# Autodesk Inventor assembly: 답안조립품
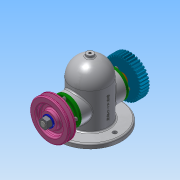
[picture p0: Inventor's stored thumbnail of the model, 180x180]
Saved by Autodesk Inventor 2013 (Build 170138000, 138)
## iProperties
Created: 2019-11
Part Number: 답안조립품
Document SubType Name: Assembly
Designer: Administrator
Author: Administrator
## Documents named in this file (14)
- C:\Users\Administrator\Desktop\491104V1020\답안조립품.iam
- C:\Users\Administrator\Desktop\491104V1020\본체.ipt
- C:\Users\Administrator\Desktop\491104V1020\축.ipt
- C:\Users\Administrator\Desktop\491104V1020\베어링 6203.ipt
- C:\Users\Administrator\Desktop\491104V1020\부시.ipt
- C:\Users\Administrator\Desktop\491104V1020\커버.ipt
- C:\Users\Administrator\Desktop\491104V1020\오일 실 26 38 8.ipt
- C:\Users\Administrator\Desktop\491104V1020\볼트 M4.ipt
- C:\Users\Administrator\Desktop\491104V1020\키 5x5x12.ipt
- C:\Users\Administrator\Desktop\491104V1020\V-벨트풀리.ipt
- V-벨트풀리.ipt
- C:\Users\Administrator\Desktop\491104V1020\스퍼기어.ipt
- C:\Users\Administrator\Desktop\491104V1020\와셔 12x24.ipt
- C:\Users\Administrator\Desktop\491104V1020\너트 M12x1.25.ipt
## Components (1 placed, 1 different names)
1. V-벨트풀리:1
